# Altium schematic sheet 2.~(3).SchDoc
size 420 x 297 mm
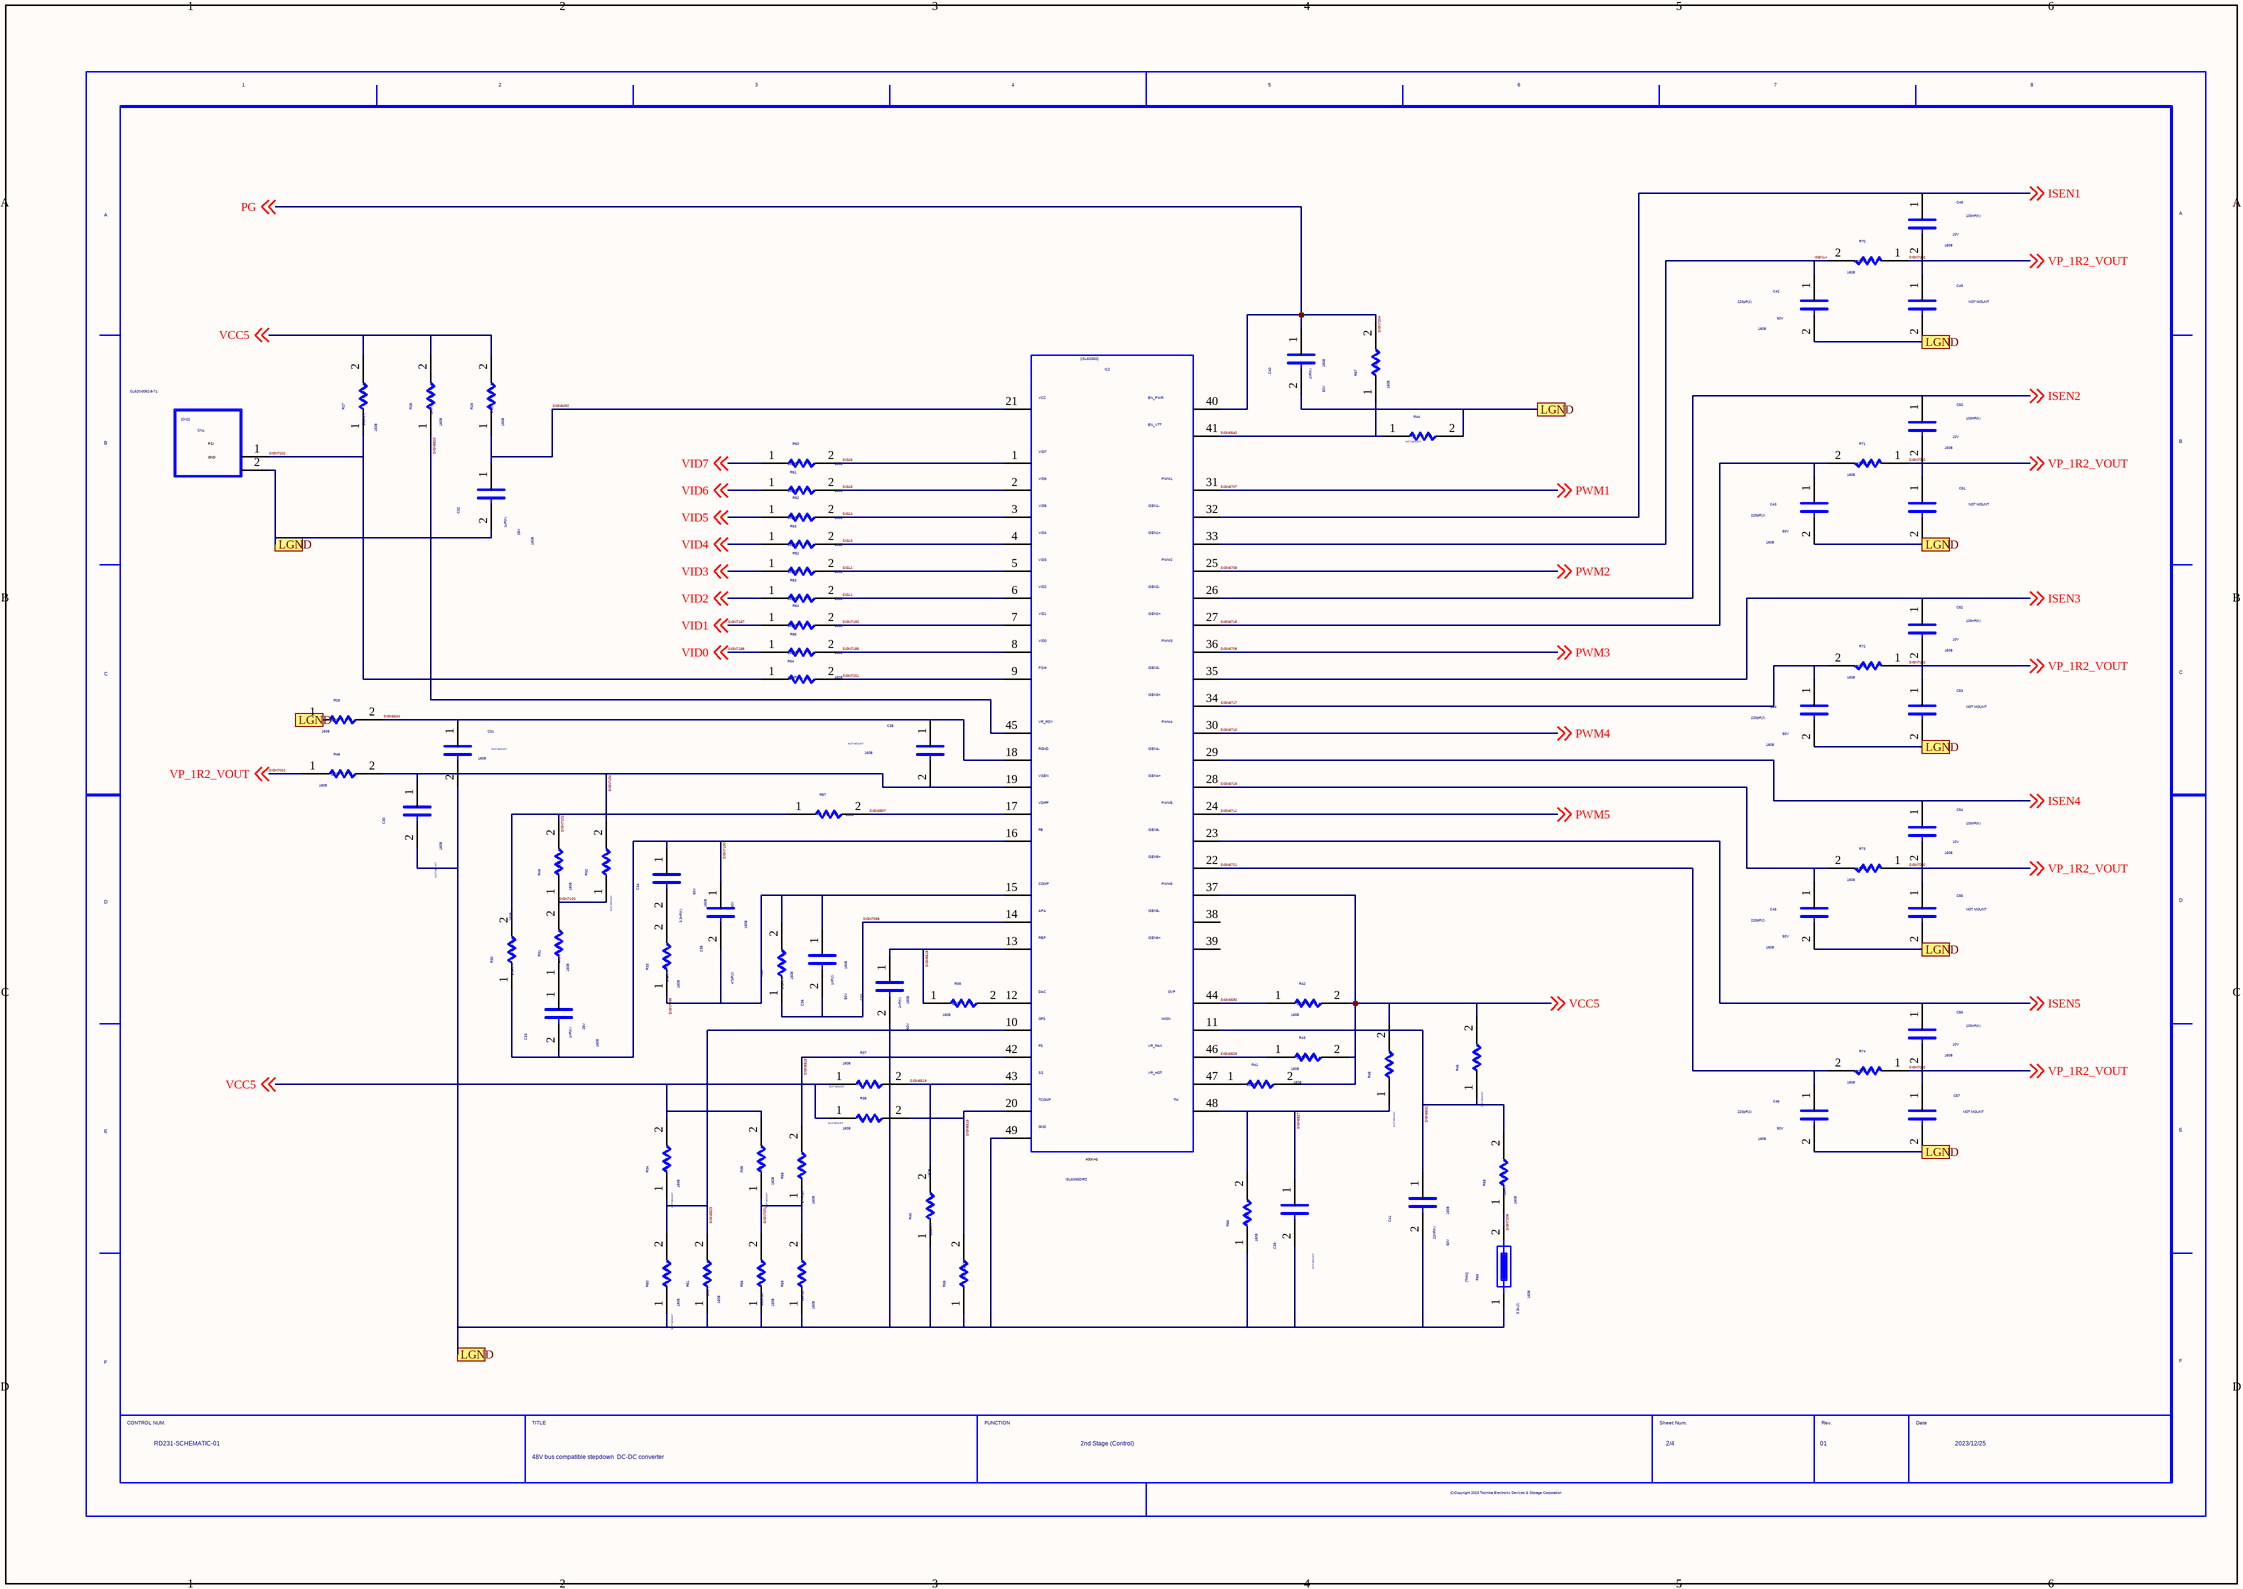
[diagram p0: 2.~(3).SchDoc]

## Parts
C30  NOTMOUNT: NOT MOUNT  SIZECODESMD: 1608  (hidden comment: C)
C31  NOTMOUNT: NOT MOUNT  SIZECODESMD: 1608  (hidden comment: C)
C32  SIZECODESMD: 1608  VAL2: 25V  VAL1: 1uF(K)  (hidden comment: C)
C33  SIZECODESMD: 1608  VAL2: 25V  VAL1: 1nF(K)  (hidden comment: C)
C34  SIZECODESMD: 1608  VAL2: 50V  VAL1: 3.3nF(K)  (hidden comment: C)
C35  SIZECODESMD: 1608  VAL2: 50V  VAL1: 47pF(J)  (hidden comment: C)
C36  SIZECODESMD: 1608  VAL2: 50V  VAL1: 1nF(J)  (hidden comment: C)
C37  SIZECODESMD: 1608  VAL2: 50V  VAL1: 1nF(K)  (hidden comment: C)
C38  NOTMOUNT: NOT MOUNT  SIZECODESMD: 1608  (hidden comment: C)
C39  NOTMOUNT: NOT MOUNT  (hidden comment: C)
C40  SIZECODESMD: 1608  VAL2: 50V  VAL1: 1nF(K)  (hidden comment: C)
C41  SIZECODESMD: 1608  VAL2: 50V  VAL1: 22nF(K)  (hidden comment: C)
C42  SIZECODESMD: 1608  VAL2: 50V  VAL1: 220pF(J)  (hidden comment: C)
C43  SIZECODESMD: 1608  VAL2: 50V  VAL1: 220pF(J)  (hidden comment: C)
C44  SIZECODESMD: 1608  VAL2: 50V  VAL1: 220pF(J)  (hidden comment: C)
C45  SIZECODESMD: 1608  VAL2: 50V  VAL1: 220pF(J)  (hidden comment: C)
C46  SIZECODESMD: 1608  VAL2: 50V  VAL1: 220pF(J)  (hidden comment: C)
C48  SIZECODESMD: 1608  VAL2: 10V  VAL1: 100nF(K)  (hidden comment: C)
C49  NOTMOUNT: NOT MOUNT  (hidden comment: C)
C50  SIZECODESMD: 1608  VAL2: 10V  VAL1: 100nF(K)  (hidden comment: C)
C51  NOTMOUNT: NOT MOUNT  (hidden comment: C)
C52  SIZECODESMD: 1608  VAL2: 10V  VAL1: 100nF(K)  (hidden comment: C)
C53  NOTMOUNT: NOT MOUNT  (hidden comment: C)
C54  SIZECODESMD: 1608  VAL2: 10V  VAL1: 100nF(K)  (hidden comment: C)
C55  NOTMOUNT: NOT MOUNT  (hidden comment: C)
C56  SIZECODESMD: 1608  VAL2: 10V  VAL1: 100nF(K)  (hidden comment: C)
C57  NOTMOUNT: NOT MOUNT  (hidden comment: C)
CN1  VAL3: CL620-0052-8-71  (hidden comment: CN2)
IC2  VAL3: ISL6336DIRZ  (hidden comment: ISL6336D)
R26  SIZECODESMD: 1608  VAL1: 10(F)  (hidden comment: R)
R27  SIZECODESMD: 1608  VAL1: 100k(F)  (hidden comment: R)
R28  SIZECODESMD: 1608  VAL1: 1k(F)  (hidden comment: R)
R29  SIZECODESMD: 1608  VAL1: 2.2(F)  (hidden comment: R)
R30  SIZECODESMD: 1608  VAL1: 1.5k(F)  (hidden comment: R)
R31  SIZECODESMD: 1608  VAL1: 47(F)  (hidden comment: R)
R32  NOTMOUNT: NOT MOUNT  (hidden comment: R)
R33  SIZECODESMD: 1608  VAL1: 3.3k(F)  (hidden comment: R)
R34  SIZECODESMD: 1608  NOTMOUNT: NOT MOUNT  (hidden comment: R)
R35  SIZECODESMD: 1608  NOTMOUNT: NOT MOUNT  (hidden comment: R)
R36  SIZECODESMD: 1608  VAL1: 8.2k(F)  (hidden comment: R)
R37  SIZECODESMD: 1608  NOTMOUNT: NOT MOUNT  (hidden comment: R)
R38  SIZECODESMD: 1608  NOTMOUNT: NOT MOUNT  (hidden comment: R)
R39  SIZECODESMD: 1608  VAL1: 1k(F)  (hidden comment: R)
R40  SIZECODESMD: 1608  VAL1: 100k(F)  (hidden comment: R)
R41  SIZECODESMD: 1608  VAL1: 10k(F)  (hidden comment: R)
R42  SIZECODESMD: 1608  VAL1: 1k(F)  (hidden comment: R)
R43  SIZECODESMD: 1608  VAL1: 1k(F)  (hidden comment: R)
R44  NOTMOUNT: NOT MOUNT  (hidden comment: R)
R45  NOTMOUNT: NOT MOUNT  (hidden comment: R)
R46  NOTMOUNT: NOT MOUNT  (hidden comment: R)
R48  SIZECODESMD: 1608  VAL1: 10(F)  (hidden comment: R)
R49  SIZECODESMD: 1608  VAL1: 0  (hidden comment: R)
R50  SIZECODESMD: 1608  NOTMOUNT: NOT MOUNT  (hidden comment: R)
R51  SIZECODESMD: 1608  VAL1: 1M(F)  (hidden comment: R)
R52  SIZECODESMD: 1608  VAL1: 100(F)  (hidden comment: R)
R53  SIZECODESMD: 1608  VAL1: 100(F)  (hidden comment: R)
R54  SIZECODESMD: 1608  VAL1: 100(F)  (hidden comment: R)
R55  SIZECODESMD: 1608  VAL1: 100(F)  (hidden comment: R)
R56  SIZECODESMD: 1608  VAL1: 220k(D)  (hidden comment: R)
R57  SIZECODESMD: 1608  VAL1: 0  (hidden comment: R)
R58  SIZECODESMD: 1608  VAL1: 2.7k(D)  (hidden comment: R)
R59  SIZECODESMD: 1608  VAL1: 82k(D)  (hidden comment: R)
R60  SIZECODESMD: 1608  VAL1: 100(F)  (hidden comment: R)
R61  SIZECODESMD: 1608  VAL1: 100(F)  (hidden comment: R)
R62  SIZECODESMD: 1608  VAL1: 100(F)  (hidden comment: R)
R63  SIZECODESMD: 1608  VAL1: 100(F)  (hidden comment: R)
R64  SIZECODESMD: 1608  VAL1: 100(F)  (hidden comment: R)
R65  SIZECODESMD: 1608  VAL1: 0  (hidden comment: R)
R66  SIZECODESMD: 1608  VAL1: 0  (hidden comment: R)
R67  SIZECODESMD: 1608  VAL1: 0  (hidden comment: R)
R68  SIZECODESMD: 1608  VAL1: 11k(F)  (hidden comment: R)
R69  SIZECODESMD: 1608  VAL1: 3.3k(J)  (hidden comment: THM)
R70  SIZECODESMD: 1608  VAL1: 130(F)  (hidden comment: R)
R71  SIZECODESMD: 1608  VAL1: 130(F)  (hidden comment: R)
R72  SIZECODESMD: 1608  VAL1: 130(F)  (hidden comment: R)
R73  SIZECODESMD: 1608  VAL1: 130(F)  (hidden comment: R)
R74  SIZECODESMD: 1608  VAL1: 130(F)  (hidden comment: R)
U?  DATE: 2023/12/25  TITLE: 48V bus compatible stepdown / DC-DC converter  REVISION: 01  SHEETNUMBER: 2/4  DRAWINGNUMBER: RD231-SCHEMATIC-01  FUNCTION: 2nd Stage (Control)  (hidden comment: WAKU_DEF100)

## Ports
LGND

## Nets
ISEN1: C48.1 IC2.32 ; off-sheet ISEN1
ISEN1+: C42.1 IC2.33 R70.2
ISEN2: C50.1 IC2.26 ; off-sheet ISEN2
ISEN3: C52.1 IC2.35 ; off-sheet ISEN3
ISEN4: C54.1 IC2.29 ; off-sheet ISEN4
ISEN5: C56.1 IC2.23 ; off-sheet ISEN5
LGND: C30.2 C31.2 C32.2 C37.2 C39.2 C40.2 C41.2 C42.2 C43.2 C44.2 C45.2 C46.2 C49.2 C51.2 C53.2 C55.2 C57.2 CN1.2 IC2.49 R26.1 R40.1 R44.2 R50.1 R51.1 R56.1 R59.1 R65.1 R66.1 R69.1 ; port LGND
SIG11: IC2.6 R53.2
SIG12: IC2.5 R52.2
SIG13: IC2.4 R63.2
SIG14: IC2.3 R62.2
SIG15: IC2.2 R61.2
SIG16: IC2.1 R60.2
SIGN6492: C32.1 IC2.21 R29.1
SIGN6507: IC2.17 R57.2
SIGN6515: C37.1 IC2.13 R39.1
SIGN6516: IC2.20 R38.2 R65.2
SIGN6519: IC2.43 R37.2 R40.2
SIGN6523: IC2.10 R34.1 R50.2 R51.2
SIGN6527: C39.1 IC2.48 R45.1 R66.2
SIGN6529: IC2.46 R43.1
SIGN6530: IC2.44 R42.1
SIGN6532: C41.1 IC2.11 R46.1 R68.2
SIGN6534: C31.1 C38.1 IC2.18 R26.2
SIGN6540: IC2.41 R44.1 R67.1
SIGN6707: IC2.31 ; off-sheet PWM1  [also labelled PWM1]
SIGN6708: IC2.25 ; off-sheet PWM2  [also labelled PWM2]
SIGN6709: IC2.36 ; off-sheet PWM3  [also labelled PWM3]
SIGN6710: IC2.30 ; off-sheet PWM4  [also labelled PWM4]
SIGN6711: IC2.24 ; off-sheet PWM5  [also labelled PWM5]
SIGN6715: C43.1 IC2.27 R71.2
SIGN6717: C44.1 IC2.34 R72.2
SIGN6719: C45.1 IC2.28 R73.2
SIGN6721: C46.1 IC2.22 R74.2
SIGN6816: IC2.42 R58.2
SIGN6820: IC2.45 R28.1
SIGN7001: R35.1 R56.2 R58.1 R59.2
SIGN7002: C48.2 C49.1 C50.2 C51.1 C52.2 C53.1 C54.2 C55.1 C56.2 C57.1 R48.1 R70.1 R71.1 R72.1 R73.1 R74.1 ; off-sheet VP_1R2_VOUT  [also labelled VP_1R2_VOUT]
SIGN7098: C36.2 IC2.14 R36.1
SIGN7099: C35.2 C36.1 IC2.15 R33.1 R36.2
SIGN7100: C33.2 C34.1 C35.1 IC2.16 R30.1
SIGN7102: R30.2 R49.2 R57.1
SIGN7103: R31.2 R32.1 R49.1
SIGN7104: C30.1 C38.2 IC2.19 R32.2 R48.2
SIGN7185: IC2.8 R55.2
SIGN7186: R55.1 ; off-sheet VID0  [also labelled VID0]
SIGN7187: R54.1 ; off-sheet VID1  [also labelled VID1]
SIGN7192: IC2.7 R54.2
SIGN7201: IC2.9 R64.2
SIGN7202: CN1.1 R27.1 R64.1
SIGN7204: C40.1 IC2.40 R67.2 ; off-sheet PG  [also labelled PG]
SIGN7206: R68.1 R69.2
VCC5: IC2.37 R27.2 R28.2 R29.2 R34.2 R35.2 R37.1 R38.1 R41.2 R42.2 R43.2 R45.2 R46.2 ; off-sheet VCC5
VID2: R53.1 ; off-sheet VID2
VID3: R52.1 ; off-sheet VID3
VID4: R63.1 ; off-sheet VID4
VID5: R62.1 ; off-sheet VID5
VID6: R61.1 ; off-sheet VID6
VID7: R60.1 ; off-sheet VID7
NetC33_1: C33.1 R31.1
NetC34_2: C34.2 R33.2
NetIC2_12: IC2.12 R39.2
NetIC2_47: IC2.47 R41.1

Not connected (* = marked no-connect by the designer): IC2 38 39

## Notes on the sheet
- (near CN1) PSI
- (near CN1) GND
- (near IC2) 400kHz

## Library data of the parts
C30 C31 C38 = C: FNPARTSNAMEG: CHIP CERAMIC CAPACITOR (1608); USEINPARTSLIST: YES; OriginalSymbolOrigin: (2540,7620); TOLERANCE: K; MAXGCOUNT: 1; COMPONENTNAME: G36030011310_package; MFSOLDERINGPROP: .; MFPACKAGEMETHOP: S; MFFORMINGDIVP: KC; COMP: G36030011310; MFMOUNTSYMBOLP: 80; PCODE: P03039AAN526; FNCLASSCODEG: P03-03
C32 = C: FNPARTSNAMEG: CHIP CERAMIC CAPACITOR (1608); USEINPARTSLIST: YES; OriginalSymbolOrigin: (2540,7620); MAXGCOUNT: 1; COMPONENTNAME: G36030011433_package; MFSOLDERINGPROP: .; MFPACKAGEMETHOP: S; MFFORMINGDIVP: KC; COMP: G36030011433; MFMOUNTSYMBOLP: 80; PCODE: P03039992230; FNCLASSCODEG: P03-03
C33 = C: FNPARTSNAMEG: CHIP CERAMIC CAPACITOR (1608); USEINPARTSLIST: YES; OriginalSymbolOrigin: (2540,7620); TOLERANCE: K; MAXGCOUNT: 1; COMPONENTNAME: G36030011297_package; MFSOLDERINGPROP: .; MFPACKAGEMETHOP: S; MFFORMINGDIVP: KC; COMP: G36030011297; MFMOUNTSYMBOLP: 80; PCODE: P03039008221; FNCLASSCODEG: P03-03
C34 = C: FNPARTSNAMEG: CHIP CERAMIC CAPACITOR (1608); USEINPARTSLIST: YES; OriginalSymbolOrigin: (2540,7620); TOLERANCE: K; MAXGCOUNT: 1; COMPONENTNAME: G36030011037_package; MFSOLDERINGPROP: .; MFPACKAGEMETHOP: S; MFFORMINGDIVP: KC; COMP: G36030011037; MFMOUNTSYMBOLP: 80; PCODE: P03039A0T125; FNCLASSCODEG: P03-03
C35 = C: FNPARTSNAMEG: CHIP CERAMIC CAPACITOR (1608); USEINPARTSLIST: YES; OriginalSymbolOrigin: (2540,7620); TOLERANCE: K; MAXGCOUNT: 1; COMPONENTNAME: G36030011303_package; MFSOLDERINGPROP: .; MFPACKAGEMETHOP: S; MFFORMINGDIVP: KC; COMP: G36030011303; MFMOUNTSYMBOLP: 80; PCODE: P03039A0P127; FNCLASSCODEG: P03-03
C36 = C: FNPARTSNAMEG: CHIP CERAMIC CAPACITOR (1608); USEINPARTSLIST: YES; OriginalSymbolOrigin: (2540,7620); MAXGCOUNT: 1; COMPONENTNAME: G36030011747_package; MFSOLDERINGPROP: .; MFPACKAGEMETHOP: S; MFFORMINGDIVP: KC; COMP: G36030011747; MFMOUNTSYMBOLP: 80; PCODE: P03190012112; FNCLASSCODEG: P03-03
C37 C40 = C: FNPARTSNAMEG: CHIP CERAMIC CAPACITOR (1608); USEINPARTSLIST: YES; OriginalSymbolOrigin: (2540,7620); TOLERANCE: K; MAXGCOUNT: 1; COMPONENTNAME: G36030011044_package; MFSOLDERINGPROP: .; MFPACKAGEMETHOP: S; MFFORMINGDIVP: KC; COMP: G36030011044; MFMOUNTSYMBOLP: 80; PCODE: P03039045226; FNCLASSCODEG: P03-03
C39 = C: FNPARTSNAMEG: CHIP CERAMIC CAPACITOR (1608); USEINPARTSLIST: YES; OriginalSymbolOrigin: (2540,7620); TOLERANCE: K; MAXGCOUNT: 1; COMPONENTNAME: G36030011310_package; MFSOLDERINGPROP: .; MFPACKAGEMETHOP: S; MFFORMINGDIVP: KC; COMP: G36030011310; SIZECODESMD: 1608; MFMOUNTSYMBOLP: 80; PCODE: P03039AAN526; FNCLASSCODEG: P03-03
C41 = C: FNPARTSNAMEG: CHIP CERAMIC CAPACITOR (1608); USEINPARTSLIST: YES; OriginalSymbolOrigin: (2540,7620); TOLERANCE: K; PCODE: P03039008221; MAXGCOUNT: 1; COMPONENTNAME: G36030011297_package; MFSOLDERINGPROP: .; MFPACKAGEMETHOP: S; MFFORMINGDIVP: KC; COMP: G36030011297; MFMOUNTSYMBOLP: 80; FNCLASSCODEG: P03-03
C42-C46 = C: FNPARTSNAMEG: CHIP CERAMIC CAPACITOR (1608); USEINPARTSLIST: YES; OriginalSymbolOrigin: (2540,7620); MAXGCOUNT: 1; COMPONENTNAME: G36030011488_package; MFSOLDERINGPROP: .; MFPACKAGEMETHOP: S; MFFORMINGDIVP: KC; COMP: G36030011488; MFMOUNTSYMBOLP: 80; PCODE: P03039269127; FNCLASSCODEG: P03-03
C48 C50 C52 C54 C56 = C: FNPARTSNAMEG: CHIP CERAMIC CAPACITOR (1608); USEINPARTSLIST: YES; OriginalSymbolOrigin: (2540,7620); MAXGCOUNT: 1; COMPONENTNAME: GDM030000714_package; MFSOLDERINGPROP: .; MFPACKAGEMETHOP: S; MFFORMINGDIVP: KC; COMP: GDM030000714; MFMOUNTSYMBOLP: 80; PCODE: P03039ABE123; FNCLASSCODEG: P03-03
C49 C51 C53 C55 C57 = C: FNPARTSNAMEG: CHIP CERAMIC CAPACITOR (1608); USEINPARTSLIST: YES; OriginalSymbolOrigin: (2540,7620); MAXGCOUNT: 1; COMPONENTNAME: G36030104128_package; MFSOLDERINGPROP: .; MFPACKAGEMETHOP: S; MFFORMINGDIVP: KC; COMP: G36030104128; SIZECODESMD: 1608; MFMOUNTSYMBOLP: 80; PCODE: P03039ABG127; FNCLASSCODEG: P03-03
CN1 = CN2: USEINPARTSLIST: YES; OUMEPARTTYPE: PJ; OriginalSymbolOrigin: (2540,15240); MAXGCOUNT: 1; COMPONENTNAME: ZS_DPJ028_package; QUADMODEL: dummymodel; COMP: ZS_DPJ028
IC2 = ISL6336D: USEINPARTSLIST: YES; TIME: 17:42:33; UPDATEUSER: q91866sr; UPDATETIME: 10:56:10; SAVECOUNT: 140; SAVEAREA0: -131159,-2851,167371,162238; OriginalSymbolOrigin: (5080,152400); MAXGCOUNT: 1; COMPONENTNAME: ISL6336D.ISL6336D; OUMEMAKER: Renesas
R26 = R: FNPARTSNAMEG: CHIP RESISTOR (1608); USEINPARTSLIST: YES; OriginalSymbolOrigin: (5080,5080); COMPONENTNAME: G36010104063_package; FUNCN: G36010104063; TOLERANCE: F; MFSOLDERINGPROP: .; MFPACKAGEMETHOP: S; MFFORMINGDIVP: KC; MFMOUNTSYMBOLP: 80; NUMBEROFELEMENT: 0; PCODE: P01042036620; VAL2: 100mW; FNCLASSCODEG: P01-08
R27 = R: FNPARTSNAMEG: CHIP RESISTOR (1608); USEINPARTSLIST: YES; OriginalSymbolOrigin: (5080,5080); COMPONENTNAME: G36010027133_package; FUNCN: G36010027133; TOLERANCE: F; MFSOLDERINGPROP: .; MFPACKAGEMETHOP: S; MFFORMINGDIVP: KC; MFMOUNTSYMBOLP: 80; NUMBEROFELEMENT: 0; VAL2: 100mW; PCODE: P01042045226; FNCLASSCODEG: P01-08
R28 = R: FNPARTSNAMEG: CHIP RESISTOR (1608); USEINPARTSLIST: YES; OriginalSymbolOrigin: (5080,5080); MAXGCOUNT: 1; COMPONENTNAME: G36010027324_package; FUNCN: G36010027324; TOLERANCE: F; MFSOLDERINGPROP: .; MFPACKAGEMETHOP: S; MFFORMINGDIVP: KC; MFMOUNTSYMBOLP: 80; NUMBEROFELEMENT: 0; VAL2: 100mW; PCODE: P01042521225; FNCLASSCODEG: P01-08
R29 = R: FNPARTSNAMEG: CHIP RESISTOR (1608); USEINPARTSLIST: YES; OriginalSymbolOrigin: (5080,5080); COMPONENTNAME: G36010141013_package; FUNCN: G36010141013; MFMOUNTSYMBOLP: 80; MFSOLDERINGPROP: .; MFPACKAGEMETHOP: S; MFFORMINGDIVP: KC; NUMBEROFELEMENT: 0; VAL2: 100mW; PCODE: P01183001112; FNCLASSCODEG: P01-08
R30 = R: FNPARTSNAMEG: CHIP RESISTOR (1608); USEINPARTSLIST: YES; OriginalSymbolOrigin: (5080,5080); COMPONENTNAME: G36010104339_package; FUNCN: G36010104339; MFSOLDERINGPROP: .; MFPACKAGEMETHOP: S; MFFORMINGDIVP: KC; MFMOUNTSYMBOLP: 80; NUMBEROFELEMENT: 0; PCODE: P01042159428; VAL2: 100mW; FNCLASSCODEG: P01-08
R31 = R: FNPARTSNAMEG: CHIP JUMPER 1608TYPE; USEINPARTSLIST: YES; PARTCOMMENT: 代表セル<KC0008> がフットプリントに登録されていません。; OriginalSymbolOrigin: (5080,5080); MAXGCOUNT: 1; COMPONENTNAME: K0100346_package; FUNCN: K0100346; VAL2: 100mW; FNCLASSCODEG: P01-08
R32 R44 = R: FNPARTSNAMEG: CHIP RESISTOR (1608); USEINPARTSLIST: YES; OriginalSymbolOrigin: (5080,5080); SIZECODESMD: 1608; COMPONENTNAME: G36010129400_package; FUNCN: G36010129400; PCODE: P01117044116; MFSOLDERINGPROP: .; MFPACKAGEMETHOP: S; MFFORMINGDIVP: KC; MFMOUNTSYMBOLP: 80; NUMBEROFELEMENT: 0; FNCLASSCODEG: P01-08
R33 = R: FNPARTSNAMEG: CHIP RESISTOR (1608); USEINPARTSLIST: YES; OriginalSymbolOrigin: (5080,5080); MAXGCOUNT: 1; COMPONENTNAME: G36010104353_package; FUNCN: G36010104353; MFSOLDERINGPROP: .; MFPACKAGEMETHOP: S; MFFORMINGDIVP: KC; MFMOUNTSYMBOLP: 80; NUMBEROFELEMENT: 0; PCODE: P01042007620; VAL2: 100mW; FNCLASSCODEG: P01-08
R34 R35 R37 = R: FNPARTSNAMEG: CHIP RESISTOR (1608); USEINPARTSLIST: YES; OriginalSymbolOrigin: (5080,5080); COMPONENTNAME: G36010129400_package; FUNCN: G36010129400; PCODE: P01117044116; MFSOLDERINGPROP: .; MFPACKAGEMETHOP: S; MFFORMINGDIVP: KC; MFMOUNTSYMBOLP: 80; NUMBEROFELEMENT: 0; FNCLASSCODEG: P01-08
R36 = R: FNPARTSNAMEG: CHIP RESISTOR (1608); USEINPARTSLIST: YES; OriginalSymbolOrigin: (5080,5080); COMPONENTNAME: G36010027188_package; FUNCN: G36010027188; TOLERANCE: F; MFSOLDERINGPROP: .; MFPACKAGEMETHOP: S; MFFORMINGDIVP: KC; MFMOUNTSYMBOLP: 80; NUMBEROFELEMENT: 0; PCODE: P01042507328; VAL2: 100mW; FNCLASSCODEG: P01-08
R38 = R: FNPARTSNAMEG: CHIP RESISTOR (1608); USEINPARTSLIST: YES; OriginalSymbolOrigin: (5080,5080); COMPONENTNAME: G36010027034_package; FUNCN: G36010027034; TOLERANCE: F; MFSOLDERINGPROP: .; MFPACKAGEMETHOP: S; MFFORMINGDIVP: KC; MFMOUNTSYMBOLP: 80; NUMBEROFELEMENT: 0; PCODE: P01042049A26; FNCLASSCODEG: P01-08
R39 R42 R43 = R: FNPARTSNAMEG: CHIP RESISTOR (1608); USEINPARTSLIST: YES; OriginalSymbolOrigin: (5080,5080); COMPONENTNAME: G36010027324_package; FUNCN: G36010027324; TOLERANCE: F; MFSOLDERINGPROP: .; MFPACKAGEMETHOP: S; MFFORMINGDIVP: KC; MFMOUNTSYMBOLP: 80; NUMBEROFELEMENT: 0; PCODE: P01042521225; VAL2: 100mW; FNCLASSCODEG: P01-08
R40 = R: FNPARTSNAMEG: CHIP RESISTOR (1608); USEINPARTSLIST: YES; OriginalSymbolOrigin: (5080,5080); COMPONENTNAME: G36010027133_package; FUNCN: G36010027133; TOLERANCE: F; MFSOLDERINGPROP: .; MFPACKAGEMETHOP: S; MFFORMINGDIVP: KC; MFMOUNTSYMBOLP: 80; NUMBEROFELEMENT: 0; PCODE: P01042045226; VAL2: 100mW; FNCLASSCODEG: P01-08
R41 = R: FNPARTSNAMEG: CHIP RESISTOR (1608); USEINPARTSLIST: YES; OriginalSymbolOrigin: (5080,5080); COMPONENTNAME: G36010027034_package; FUNCN: G36010027034; TOLERANCE: F; MFSOLDERINGPROP: .; MFPACKAGEMETHOP: S; MFFORMINGDIVP: KC; MFMOUNTSYMBOLP: 80; NUMBEROFELEMENT: 0; PCODE: P01042049A26; VAL2: 100mW; FNCLASSCODEG: P01-08
R45 = R: FNPARTSNAMEG: CHIP RESISTOR (1608); USEINPARTSLIST: YES; OriginalSymbolOrigin: (5080,5080); SIZECODESMD: 1608; COMPONENTNAME: G36010027324_package; FUNCN: G36010027324; TOLERANCE: F; MFSOLDERINGPROP: .; MFPACKAGEMETHOP: S; MFFORMINGDIVP: KC; MFMOUNTSYMBOLP: 80; NUMBEROFELEMENT: 0; PCODE: P01042521225; FNCLASSCODEG: P01-08
R46 = R: FNPARTSNAMEG: CHIP RESISTOR (1608); USEINPARTSLIST: YES; OriginalSymbolOrigin: (5080,5080); SIZECODESMD: 1608; COMPONENTNAME: G5101106E109_package; FUNCN: G5101106E109; MFSOLDERINGPROP: .; MFPACKAGEMETHOP: S; MFFORMINGDIVP: KC; MFMOUNTSYMBOLP: 80; NUMBEROFELEMENT: 0; PCODE: P01042153228; FNCLASSCODEG: P01-08
R48 = R: FNPARTSNAMEG: CHIP RESISTOR (1608); USEINPARTSLIST: YES; OriginalSymbolOrigin: (5080,5080); MAXGCOUNT: 1; COMPONENTNAME: G36010104063_package; FUNCN: G36010104063; TOLERANCE: F; MFSOLDERINGPROP: .; MFPACKAGEMETHOP: S; MFFORMINGDIVP: KC; MFMOUNTSYMBOLP: 80; NUMBEROFELEMENT: 0; PCODE: P01042036620; VAL2: 100mW; FNCLASSCODEG: P01-08
R49 R57 R65-R67 = R: FNPARTSNAMEG: CHIP JUMPER 1608TYPE; USEINPARTSLIST: YES; PARTCOMMENT: 代表セル<KC0008> がフットプリントに登録されていません。; OriginalSymbolOrigin: (5080,5080); MAXGCOUNT: 1; COMPONENTNAME: K0100346_package; FUNCN: K0100346; FNCLASSCODEG: P01-08
R50 = R: FNPARTSNAMEG: CHIP RESISTOR (1608); USEINPARTSLIST: YES; OriginalSymbolOrigin: (5080,5080); MAXGCOUNT: 1; COMPONENTNAME: G36010129639_package; FUNCN: G36010129639; MFSOLDERINGPROP: .; MFPACKAGEMETHOP: S; MFFORMINGDIVP: KC; MFMOUNTSYMBOLP: 80; NUMBEROFELEMENT: 0; PCODE: P01117067115; FNCLASSCODEG: P01-08
R51 = R: FNPARTSNAMEG: CHIP RESISTOR (1608); USEINPARTSLIST: YES; OriginalSymbolOrigin: (5080,5080); MAXGCOUNT: 1; COMPONENTNAME: G5101106E109_package; FUNCN: G5101106E109; MFSOLDERINGPROP: .; MFPACKAGEMETHOP: S; MFFORMINGDIVP: KC; MFMOUNTSYMBOLP: 80; NUMBEROFELEMENT: 0; PCODE: P01042153228; VAL2: 100mW; FNCLASSCODEG: P01-08
R52-R55 R60-R64 = R: FNPARTSNAMEG: CHIP RESISTOR (1608); USEINPARTSLIST: YES; OriginalSymbolOrigin: (5080,5080); MAXGCOUNT: 1; COMPONENTNAME: G36010104087_package; FUNCN: G36010104087; TOLERANCE: F; MFSOLDERINGPROP: .; MFPACKAGEMETHOP: S; MFFORMINGDIVP: KC; MFMOUNTSYMBOLP: 80; NUMBEROFELEMENT: 0; PCODE: P01042041426; VAL2: 100mW; FNCLASSCODEG: P01-08
R56 = R: FNPARTSNAMEG: CHIP RESISTOR (1608); USEINPARTSLIST: YES; OriginalSymbolOrigin: (5080,5080); MAXGCOUNT: 1; COMPONENTNAME: G36010014355_package; FUNCN: G36010014355; MFSOLDERINGPROP: .; MFPACKAGEMETHOP: S; MFFORMINGDIVP: KC; MFMOUNTSYMBOLP: 80; NUMBEROFELEMENT: 0; PCODE: P01042201820; VAL2: 62.5mW; FNCLASSCODEG: P01-08
R58 = R: FNPARTSNAMEG: CHIP RESISTOR (1608); USEINPARTSLIST: YES; OriginalSymbolOrigin: (5080,5080); MFSOLDERINGPROP: .; MFPACKAGEMETHOP: S; MFFORMINGDIVP: KC; MFMOUNTSYMBOLP: 80; NUMBEROFELEMENT: 0; PCODE: P01117039112; MAXGCOUNT: 1; COMPONENTNAME: G36010129356_package; FUNCN: G36010129356; VAL2: 62.5mW; FNCLASSCODEG: P01-08
R59 = R: FNPARTSNAMEG: CHIP RESISTOR (1608); USEINPARTSLIST: YES; OriginalSymbolOrigin: (5080,5080); MAXGCOUNT: 1; COMPONENTNAME: G36010129714_package; FUNCN: G36010129714; MFSOLDERINGPROP: .; MFPACKAGEMETHOP: S; MFFORMINGDIVP: KC; MFMOUNTSYMBOLP: 80; NUMBEROFELEMENT: 0; PCODE: P01117075110; VAL2: 62.5mW; FNCLASSCODEG: P01-08
R68 = R: FNPARTSNAMEG: CHIP RESISTOR (1608); USEINPARTSLIST: YES; OriginalSymbolOrigin: (5080,5080); MAXGCOUNT: 1; COMPONENTNAME: G36010027164_package; FUNCN: G36010027164; TOLERANCE: F; MFSOLDERINGPROP: .; MFPACKAGEMETHOP: S; MFFORMINGDIVP: KC; MFMOUNTSYMBOLP: 80; NUMBEROFELEMENT: 0; PCODE: P01042066221; VAL2: 100mW; FNCLASSCODEG: P01-08
R69 = THM: FNPARTSNAMEG: CHIP NTC THERMISTOR; USEINPARTSLIST: YES; OUMEPARTTYPE: MT; PARTCOMMENT: 代表セル<KC0008> がフットプリントに登録されていません。; SAVECOUNT: 4; SAVEAREA0: -824,-117,15885,10433; TIME: 16:37:29; UPDATEUSER: tomizawa-y; UPDATETIME: 10:51:47; OriginalSymbolOrigin: (2540,5080); DCSPARKOVERVOLT: 0.000000000000000; COMPONENTNAME: K0900027_package; MAXGCOUNT: 1; MFSOLDERINGPROP: .; MFPACKAGEMETHOP: S; MFFORMINGDIVP: KC; COMP: K0900027; MFMOUNTSYMBOLP: 80; VARISTORVOLTAGE: 0; VAL2: 100mW; FNCLASSCODEG: P09-01
R70-R74 = R: FNPARTSNAMEG: CHIP RESISTOR (1608); USEINPARTSLIST: YES; OriginalSymbolOrigin: (5080,5080); MAXGCOUNT: 1; COMPONENTNAME: G5101104N107_package; FUNCN: G5101104N107; MFSOLDERINGPROP: .; MFPACKAGEMETHOP: S; MFFORMINGDIVP: KC; MFMOUNTSYMBOLP: 80; NUMBEROFELEMENT: 0; PCODE: P01042089220; VAL2: 100mW; FNCLASSCODEG: P01-08
U? = WAKU_DEF100: PLOTTIME: HH:MM; SAVEAREA0: -56280,0,471144,298016; TIME: 20:22:11; UPDATEUSER: sptcae13; UPDATETIME: 11:35:27; SAVECOUNT: 8; OriginalSymbolOrigin: (10160,284480)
